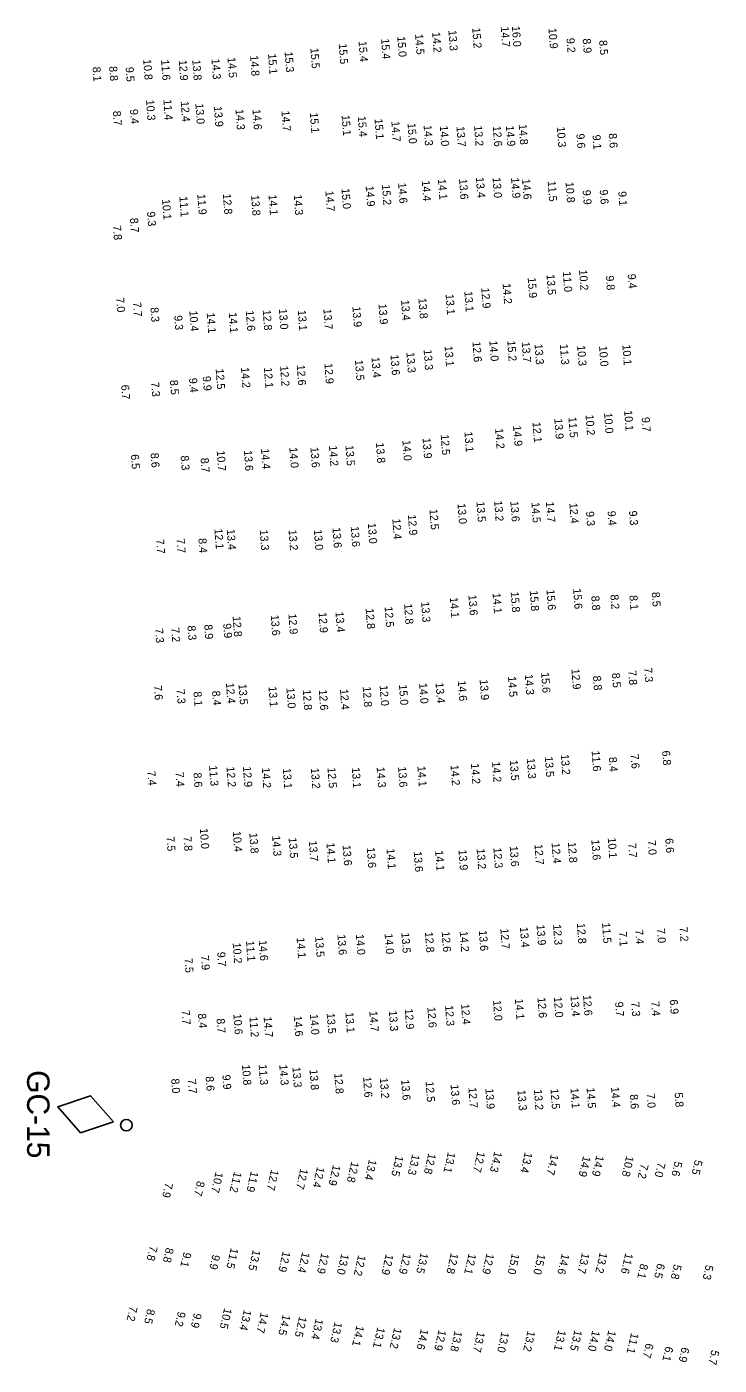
# Model space of a CAD drawing. Extents: x 815385 to 820851, y 582449 to 604245.
# Drawn here: x 820400 to 820832, y 590107 to 590943 of the extents above; entities that cross this region are included whole.
import ezdxf

# ---------------------------------------------------------------- set-up
doc = ezdxf.new("R2010")
doc.units = 0
doc.layers.add('V-CHAN-AIDS', color=7, linetype='Continuous')
doc.layers.add('V-TOPO-SOUN-021309', color=7, linetype='Continuous')

msp = doc.modelspace()

# ---------------------------------------------------------------- linework, layer by layer
at = {"layer": 'V-CHAN-AIDS'}
msp.add_lwpolyline([(820454.23, 590259), (820439.95, 590275.25), (820419.45, 590268.32), (820433.73, 590252.07)], close=True, dxfattribs=at)
msp.add_circle((820462.34, 590256.83), 3.6, dxfattribs=at)

# ---------------------------------------------------------------- texts
msp.add_text('GC-15', height=14, rotation=270, dxfattribs=at).set_placement((820400.36, 590291.23))
at = {"layer": 'V-TOPO-SOUN-021309'}
for s, rotation, p in [('14.7 ', 274.208, (820696.06, 590943.12)), ('16.0 ', 274.208, (820703.02, 590943.38)), ('15.4 ', 274.208, (820621.34, 590935.57)), ('15.0 ', 274.208, (820631.45, 590936.96)), ('14.5 ', 274.208, (820642.55, 590938.44)), ('14.2 ', 274.208, (820653.25, 590939.65)), ('13.3 ', 274.208, (820663.36, 590940.81)), ('15.2 ', 274.208, (820678.25, 590942.33)), ('10.9 ', 274.208, (820725.87, 590942.15)), ('9.2', 274.208, (820737.11, 590935.91)), ('8.9', 274.208, (820747.21, 590935.6)), ('8.5', 274.208, (820757.48, 590934.54)), ('15.1 ', 274.208, (820550.77, 590926.13)), ('15.3 ', 274.208, (820561.13, 590927.37)), ('15.5 ', 274.208, (820577.21, 590929.72)), ('15.5 ', 274.208, (820594.89, 590932.47)), ('15.4 ', 274.208, (820607.31, 590933.97)), ('8.1', 274.208, (820441.19, 590917.92)), ('8.8', 274.208, (820451.57, 590918.24)), ('9.5', 274.208, (820461.83, 590917.78)), ('10.8 ', 274.208, (820472.83, 590922.66)), ('11.6 ', 274.208, (820483.98, 590922.37)), ('12.9 ', 274.208, (820495.03, 590922.19)), ('13.8 ', 274.208, (820503.48, 590922.33)), ('14.3 ', 274.208, (820515.46, 590922.95)), ('14.5 ', 274.208, (820525.46, 590923.91)), ('14.8 ', 274.208, (820539.59, 590925.04)), ('10.3 ', 274.208, (820474.6, 590897.3)), ('11.4 ', 274.208, (820485.46, 590897.54)), ('12.4 ', 274.208, (820496.27, 590896.47)), ('13.0 ', 274.208, (820505.39, 590895.03)), ('13.9 ', 274.208, (820517, 590893.32)), ('8.7', 274.208, (820453.9, 590890.39)), ('9.4', 274.208, (820464.54, 590891.46)), ('14.3 ', 274.208, (820530.47, 590891.46)), ('14.6 ', 274.208, (820541.07, 590891.46)), ('14.7 ', 274.208, (820559.14, 590890.53)), ('15.1 ', 274.208, (820576.91, 590889.32)), ('15.1 ', 274.208, (820596.72, 590887.78)), ('15.4 ', 274.208, (820606.82, 590887.13)), ('15.1 ', 274.208, (820617.28, 590885.5)), ('14.7 ', 274.208, (820627.77, 590883.97)), ('15.0 ', 274.208, (820637.87, 590882.75)), ('14.3 ', 274.208, (820647.89, 590881.5)), ('14.0 ', 274.208, (820658.02, 590881.19)), ('13.7 ', 274.208, (820668.4, 590880.82)), ('13.2 ', 274.208, (820679.4, 590881.22)), ('12.6 ', 274.208, (820691.12, 590880.99)), ('14.9 ', 274.208, (820699.28, 590881.15)), ('14.8 ', 274.208, (820707.3, 590882.1)), ('10.3 ', 274.208, (820731.05, 590880.52)), ('9.6', 274.208, (820743.28, 590876.15)), ('8.6', 274.208, (820763.46, 590876.39)), ('9.1', 274.208, (820753.34, 590875.46)), ('14.9 ', 274.208, (820611.71, 590843.55)), ('15.2 ', 274.208, (820621.89, 590844.41)), ('14.6 ', 274.208, (820631.97, 590845.47)), ('14.4 ', 274.208, (820646.75, 590846.93)), ('14.1 ', 274.208, (820656.84, 590847.85)), ('13.6 ', 274.208, (820670, 590847.93)), ('13.4 ', 274.208, (820680.55, 590848.97)), ('13.0 ', 274.208, (820690.95, 590848.85)), ('14.9 ', 274.208, (820702.46, 590848.67)), ('14.6 ', 274.208, (820709.41, 590847.93)), ('11.5 ', 274.208, (820725.36, 590846.65)), ('10.8 ', 274.208, (820736.53, 590845.95)), ('10.1 ', 274.208, (820484.64, 590835.25)), ('11.1 ', 274.208, (820495.41, 590837.01)), ('11.9 ', 274.208, (820506.61, 590838.43)), ('12.8 ', 274.208, (820522.6, 590838.62)), ('13.8 ', 274.208, (820540.2, 590837.84)), ('14.1 ', 274.208, (820551.09, 590838.07)), ('14.3 ', 274.208, (820566.84, 590838.1)), ('14.7 ', 274.208, (820586.6, 590840.44)), ('15.0 ', 274.208, (820596.65, 590842.02)), ('9.9', 274.208, (820747.21, 590840.98)), ('9.6', 274.208, (820757.84, 590841.24)), ('9.1', 274.208, (820769.46, 590840.16)), ('9.3', 274.208, (820475.24, 590827.5)), ('7.8', 274.208, (820453.96, 590818.86)), ('8.7', 274.208, (820464.6, 590823.52)), ('15.9 ', 274.208, (820712.87, 590786.33)), ('13.5 ', 274.208, (820724.64, 590788.29)), ('11.0 ', 274.208, (820734.83, 590790.11)), ('10.2 ', 274.208, (820744.91, 590791.13)), ('9.8', 274.208, (820761.68, 590787.53)), ('9.4', 274.208, (820775.3, 590788.55)), ('13.1 ', 274.208, (820661.64, 590775.93)), ('13.1 ', 274.208, (820673.33, 590777.74)), ('12.9 ', 274.208, (820683.89, 590779.89)), ('14.2 ', 274.208, (820697.24, 590782.67)), ('7.0', 274.208, (820455.92, 590773.76)), ('7.7', 274.208, (820466.49, 590770.98)), ('8.3', 274.208, (820477.33, 590767.65)), ('13.9 ', 274.208, (820603.42, 590768.21)), ('13.9 ', 274.208, (820619.75, 590769.89)), ('13.4 ', 274.208, (820633.8, 590772.29)), ('13.8 ', 274.208, (820644.65, 590773.45)), ('9.3', 274.208, (820492.22, 590762.63)), ('10.4 ', 274.208, (820501.63, 590765.54)), ('14.1 ', 274.208, (820512.48, 590764.33)), ('14.1 ', 274.208, (820526.25, 590764.54)), ('12.6 ', 274.208, (820536.91, 590765.71)), ('12.8 ', 274.208, (820547.46, 590766.09)), ('13.0 ', 274.208, (820557.56, 590766.74)), ('13.1 ', 274.208, (820569.38, 590765.93)), ('13.7 ', 274.208, (820585.27, 590766.7)), ('13.1 ', 274.208, (820660.99, 590743.56)), ('12.6 ', 274.208, (820678.42, 590746.32)), ('14.0 ', 274.208, (820688.91, 590746.87)), ('15.2 ', 274.208, (820700.12, 590746.86)), ('13.7 ', 274.208, (820709.18, 590746.12)), ('13.3 ', 274.208, (820717.16, 590744.81)), ('11.3 ', 274.208, (820732.96, 590744.72)), ('10.3 ', 274.208, (820743.76, 590743.94)), ('10.0 ', 274.208, (820757.42, 590743.58)), ('10.1 ', 274.208, (820771.97, 590744.39)), ('13.5 ', 274.208, (820605.04, 590734.82)), ('13.4 ', 274.208, (820615.38, 590736.61)), ('13.6 ', 274.208, (820627.25, 590738.08)), ('13.3 ', 274.208, (820637.14, 590739.63)), ('13.3 ', 274.208, (820647.91, 590741.34)), ('12.5 ', 274.208, (820518.08, 590729.33)), ('14.2 ', 274.208, (820533.89, 590730.22)), ('12.1 ', 274.208, (820548.21, 590730.11)), ('12.2 ', 274.208, (820558.32, 590731.15)), ('12.6 ', 274.208, (820568.69, 590731.73)), ('12.9 ', 274.208, (820585.95, 590732.75)), ('6.7', 274.208, (820459.05, 590719.26)), ('7.3', 274.208, (820477.76, 590721.03)), ('8.5', 274.208, (820489.51, 590722.26)), ('9.4', 274.208, (820501.47, 590723.55)), ('9.9', 274.208, (820509.97, 590724.7)), ('10.2 ', 274.208, (820749.01, 590700.57)), ('10.0 ', 274.208, (820760.54, 590701.79)), ('10.1 ', 274.208, (820773.12, 590703.29)), ('14.2 ', 274.208, (820692.56, 590692.13)), ('14.9 ', 274.208, (820703.73, 590693.84)), ('12.1 ', 274.208, (820715.93, 590696)), ('13.9 ', 274.208, (820729.49, 590698.23)), ('11.5 ', 274.208, (820738.34, 590699.14)), ('9.7', 274.208, (820784.05, 590699.08)), ('14.0 ', 274.208, (820634.63, 590684.7)), ('13.9 ', 274.208, (820647.26, 590686.04)), ('12.5 ', 274.208, (820658.58, 590688.26)), ('13.1 ', 274.208, (820673.39, 590689.99)), ('6.5', 274.208, (820465.14, 590675.8)), ('8.6', 274.208, (820477.45, 590676.69)), ('8.3', 274.208, (820496.21, 590675.05)), ('10.7 ', 274.208, (820518.73, 590678.18)), ('13.6 ', 274.208, (820535.73, 590678.34)), ('14.4 ', 274.208, (820546.37, 590679.46)), ('14.0 ', 274.208, (820564.06, 590680.21)), ('13.6 ', 274.208, (820577.25, 590680.36)), ('14.2 ', 274.208, (820588.83, 590681.33)), ('13.5 ', 274.208, (820599.11, 590681.55)), ('13.8 ', 274.208, (820618.13, 590683.18)), ('8.7', 274.208, (820508.69, 590673.63)), ('13.0 ', 274.208, (820669.06, 590645.22)), ('13.5 ', 274.208, (820680.87, 590646.39)), ('13.2 ', 274.208, (820691.95, 590646.85)), ('13.6 ', 274.208, (820702.03, 590646.6)), ('14.5 ', 274.208, (820715.18, 590645.93)), ('14.7 ', 274.208, (820724.26, 590646.24)), ('12.4 ', 274.208, (820738.89, 590645.46)), ('12.4 ', 274.208, (820628.37, 590635.6)), ('12.9 ', 274.208, (820638.12, 590638.14)), ('12.5 ', 274.208, (820651.57, 590641.63)), ('9.3', 274.208, (820749.28, 590640.24)), ('9.4', 274.208, (820762.75, 590640.49)), ('9.3', 274.208, (820776.13, 590640.62)), ('12.1 ', 274.208, (820517.32, 590629.42)), ('13.4 ', 274.208, (820525, 590629.09)), ('13.3 ', 274.208, (820545.58, 590628.72)), ('13.2 ', 274.208, (820563.59, 590628.67)), ('13.0 ', 274.208, (820579.37, 590628.84)), ('13.6 ', 274.208, (820590.99, 590630.19)), ('13.6 ', 274.208, (820602.4, 590630.9)), ('13.0 ', 274.208, (820613.08, 590632.91)), ('7.7', 274.208, (820480.87, 590622.86)), ('7.7', 274.208, (820493.68, 590623.27)), ('8.4', 274.208, (820507.29, 590623.38)), ('15.6 ', 274.208, (820741.24, 590592.06)), ('13.3 ', 274.208, (820646.33, 590583.8)), ('14.1 ', 274.208, (820664.29, 590586.56)), ('13.6 ', 274.208, (820675.86, 590588.04)), ('14.1 ', 274.208, (820690.95, 590589.24)), ('15.8 ', 274.208, (820702.25, 590589.98)), ('15.8 ', 274.208, (820714.16, 590590.75)), ('15.6 ', 274.208, (820724.63, 590591.37)), ('8.8', 274.208, (820752.58, 590587.47)), ('8.2', 274.208, (820764.56, 590588.21)), ('8.1', 274.208, (820776.38, 590587.78)), ('8.5', 274.208, (820790.31, 590589.79)), ('13.6 ', 274.208, (820552.48, 590575.48)), ('12.9 ', 274.208, (820563.5, 590576.3)), ('12.9 ', 274.208, (820582.31, 590577.18)), ('13.4 ', 274.208, (820592.89, 590577.53)), ('12.8 ', 274.208, (820611.73, 590579.59)), ('12.5 ', 274.208, (820623.56, 590580.72)), ('12.8 ', 274.208, (820635.7, 590582.55)), ('7.3', 274.208, (820480.23, 590567.19)), ('7.2', 274.208, (820490.34, 590567.61)), ('8.3', 274.208, (820500.45, 590568.87)), ('8.9', 274.208, (820510.96, 590569.52)), ('9.9', 274.208, (820522.76, 590570.17)), ('12.8 ', 274.208, (820528.67, 590574.72)), ('12.9 ', 274.208, (820740.18, 590541.85)), ('7.3', 274.208, (820785.56, 590542.61)), ('13.4 ', 274.208, (820655.34, 590533.25)), ('14.6 ', 274.208, (820669.24, 590534.52)), ('13.9 ', 274.208, (820682.88, 590535.17)), ('14.5 ', 274.208, (820700.58, 590537.14)), ('14.3 ', 274.208, (820711.08, 590538.45)), ('15.6 ', 274.208, (820721.25, 590539.67)), ('8.8', 274.208, (820753.63, 590537.51)), ('8.5', 274.208, (820765.46, 590539.26)), ('7.8', 274.208, (820775.67, 590540.82)), ('7.6', 274.208, (820479.5, 590531.47)), ('7.3', 274.208, (820493.68, 590529.18)), ('8.1', 274.208, (820504.25, 590527.65)), ('8.4', 274.208, (820515.82, 590528.13)), ('12.4 ', 274.208, (820524.5, 590533.06)), ('13.5 ', 274.208, (820532.34, 590532.36)), ('13.1 ', 274.208, (820551.08, 590530.85)), ('13.0 ', 274.208, (820562.23, 590530.01)), ('12.8 ', 274.208, (820572.45, 590528.88)), ('12.6 ', 274.208, (820582.49, 590528.82)), ('12.4 ', 274.208, (820595.71, 590529.18)), ('12.8 ', 274.208, (820609.87, 590530.78)), ('12.0 ', 274.208, (820620.47, 590531.57)), ('15.0 ', 274.208, (820632.51, 590532.01)), ('14.0 ', 274.208, (820645.08, 590532.96)), ('14.2 ', 274.208, (820690.62, 590483.86)), ('13.5 ', 274.208, (820701.7, 590484.86)), ('13.3 ', 274.208, (820712.31, 590486.01)), ('13.5 ', 274.208, (820723.55, 590487.1)), ('13.2 ', 274.208, (820733.57, 590488.46)), ('11.6 ', 274.208, (820752.81, 590490.67)), ('8.4', 274.208, (820763.53, 590486.73)), ('7.6', 274.208, (820777.14, 590488.64)), ('6.8', 274.208, (820796.79, 590490.72)), ('7.4', 274.208, (820475.41, 590478.11)), ('7.4', 274.208, (820493.03, 590477.37)), ('8.6', 274.208, (820504.18, 590476.97)), ('11.3 ', 274.208, (820513.97, 590481.47)), ('12.2 ', 274.208, (820524.84, 590480.77)), ('12.9 ', 274.208, (820535.11, 590480.82)), ('14.2 ', 274.208, (820546.87, 590480.17)), ('13.1 ', 274.208, (820559.99, 590479.76)), ('13.2 ', 274.208, (820577.52, 590479.85)), ('12.5 ', 274.208, (820587.9, 590480.21)), ('13.1 ', 274.208, (820603.05, 590480.25)), ('14.3 ', 274.208, (820618.57, 590480.5)), ('13.6 ', 274.208, (820631.94, 590480.74)), ('14.1 ', 274.208, (820644.01, 590481.1)), ('14.2 ', 274.208, (820664.72, 590481.8)), ('14.2 ', 274.208, (820677.44, 590482.74)), ('10.0 ', 274.208, (820508.21, 590442.23)), ('7.5', 274.208, (820487.34, 590437.09)), ('7.8', 274.208, (820497.97, 590437.15)), ('10.4 ', 274.208, (820528.78, 590440.41)), ('13.8 ', 274.208, (820539.07, 590439.35)), ('14.3 ', 274.208, (820553.29, 590437.67)), ('13.5 ', 274.208, (820563.62, 590436.41)), ('13.7 ', 274.208, (820576.22, 590434.42)), ('14.1 ', 274.208, (820587.24, 590433.26)), ('12.4 ', 274.208, (820727.82, 590433.14)), ('12.8 ', 274.208, (820738, 590433.56)), ('13.6 ', 274.208, (820752.6, 590435.16)), ('10.1 ', 274.208, (820762.86, 590436.4)), ('7.7', 274.208, (820775.6, 590432.92)), ('7.0', 274.208, (820787.79, 590434.76)), ('6.6', 274.208, (820798.73, 590435.93)), ('13.6 ', 274.208, (820597.33, 590431.73)), ('13.6 ', 274.208, (820612.42, 590430.33)), ('14.1 ', 274.208, (820624.74, 590429.56)), ('13.6 ', 274.208, (820641.72, 590427.82)), ('14.1 ', 274.208, (820655.1, 590428.41)), ('13.9 ', 274.208, (820669.7, 590428.86)), ('13.2 ', 274.208, (820681.01, 590429.51)), ('12.3 ', 274.208, (820691.45, 590430.12)), ('13.6 ', 274.208, (820701.65, 590431.17)), ('12.7 ', 274.208, (820717.14, 590432.3)), ('12.8 ', 274.208, (820743.62, 590382.96)), ('11.5 ', 274.208, (820759.28, 590383.22)), ('13.5 ', 274.208, (820580.16, 590374.64)), ('13.6 ', 274.208, (820594.1, 590375.91)), ('14.0 ', 274.208, (820605.63, 590376.02)), ('14.0 ', 274.208, (820623.56, 590376.48)), ('13.5 ', 274.208, (820633.96, 590377.08)), ('12.8 ', 274.208, (820648.73, 590377.47)), ('12.6 ', 274.208, (820659.2, 590377.75)), ('14.2 ', 274.208, (820670.43, 590377.94)), ('13.6 ', 274.208, (820682.4, 590378.46)), ('12.7 ', 274.208, (820695.81, 590379.63)), ('13.4 ', 274.208, (820708.02, 590380.56)), ('13.9 ', 274.208, (820718.42, 590381.97)), ('12.3 ', 274.208, (820728.71, 590382.18)), ('7.1', 274.208, (820769.76, 590377.65)), ('7.4', 274.208, (820779.9, 590378.99)), ('7.0', 274.208, (820793.55, 590379.68)), ('7.2', 274.208, (820807.64, 590380.6)), ('10.2 ', 274.208, (820528.71, 590370.7)), ('11.1 ', 274.208, (820537.02, 590371.94)), ('14.6 ', 274.208, (820544.98, 590372.31)), ('14.1 ', 274.208, (820568.59, 590373.96)), ('7.5', 274.208, (820498.6, 590361.1)), ('7.9', 274.208, (820508.84, 590362.83)), ('9.7', 274.208, (820519.05, 590364.97)), ('12.4 ', 274.208, (820671.28, 590332.52)), ('12.0 ', 274.208, (820691.24, 590334.82)), ('14.1 ', 274.208, (820704.91, 590335.7)), ('12.6 ', 274.208, (820719.01, 590336.57)), ('12.0 ', 274.208, (820729.23, 590336.89)), ('13.4 ', 274.208, (820739.63, 590337.59)), ('12.6 ', 274.208, (820747.41, 590338.04)), ('9.7', 274.208, (820767.44, 590333.8)), ('7.3', 274.208, (820777.53, 590333.81)), ('7.4', 274.208, (820790.04, 590334.12)), ('6.9', 274.208, (820801.52, 590335.27)), ('7.7', 274.208, (820496.84, 590328.62)), ('8.4', 274.208, (820507.04, 590326.55)), ('10.6 ', 274.208, (820529.11, 590326.25)), ('11.2 ', 274.208, (820539.17, 590324.54)), ('14.7 ', 274.208, (820548.03, 590324.53)), ('14.6 ', 274.208, (820566.83, 590325.07)), ('14.0 ', 274.208, (820576.94, 590326.13)), ('13.5 ', 274.208, (820587.39, 590326.78)), ('13.1 ', 274.208, (820599.08, 590327.3)), ('14.7 ', 274.208, (820614.02, 590328.03)), ('13.3 ', 274.208, (820626.18, 590328.3)), ('12.9 ', 274.208, (820636.15, 590329.51)), ('12.6 ', 274.208, (820650.24, 590330.52)), ('12.3 ', 274.208, (820661.3, 590331.61)), ('8.7', 274.208, (820518.65, 590323.4)), ('10.8 ', 274.208, (820534.49, 590294.56)), ('11.3 ', 274.208, (820544.93, 590294.7)), ('14.3 ', 274.208, (820557.8, 590294.57)), ('13.3 ', 274.208, (820565.98, 590293.14)), ('13.8 ', 274.208, (820576.7, 590291.55)), ('8.0', 274.208, (820490.33, 590285.81)), ('7.7', 274.208, (820500.75, 590285.59)), ('8.6', 274.208, (820511.81, 590287.24)), ('9.9', 274.208, (820522.26, 590288.23)), ('12.8 ', 274.208, (820592.13, 590289.2)), ('12.6 ', 274.208, (820610.1, 590286.97)), ('13.2 ', 274.208, (820620.57, 590286.32)), ('13.6 ', 274.208, (820633.92, 590285.17)), ('12.5 ', 274.208, (820649.15, 590284.04)), ('13.6 ', 274.208, (820664.75, 590282.14)), ('12.7 ', 274.208, (820675.89, 590280.38)), ('13.9 ', 274.208, (820686.44, 590279.69)), ('13.3 ', 274.208, (820706.53, 590278.74)), ('13.2 ', 274.208, (820716.79, 590279.09)), ('12.5 ', 274.208, (820727.12, 590279.61)), ('14.1 ', 274.208, (820739.59, 590280.01)), ('14.5 ', 274.208, (820749.64, 590280.16)), ('14.4 ', 274.208, (820764.9, 590280.64)), ('8.6', 274.208, (820776.67, 590275.99)), ('7.0', 274.208, (820787.16, 590276.64)), ('5.8', 274.208, (820804.6, 590277.15)), ('12.7 ', 257.192, (820681.59, 590240.67)), ('14.3 ', 257.192, (820692.14, 590240.75)), ('12.9 ', 257.192, (820591.36, 590232.34)), ('12.8 ', 257.192, (820602.83, 590234.34)), ('13.4 ', 257.192, (820613.88, 590235.76)), ('13.5 ', 257.192, (820630.59, 590238.16)), ('13.3 ', 257.192, (820640.85, 590238.96)), ('12.8 ', 257.192, (820650.94, 590239.58)), ('13.1 ', 257.192, (820663.14, 590240.28)), ('13.4 ', 257.192, (820711.15, 590240.26)), ('14.7 ', 257.192, (820727.43, 590239)), ('14.9 ', 257.192, (820747.51, 590237.86)), ('14.9 ', 257.192, (820755.81, 590238.19)), ('10.8 ', 257.192, (820774.47, 590237.96)), ('7.2', 257.192, (820783.61, 590233.06)), ('7.0', 257.192, (820794.15, 590233.99)), ('5.6', 257.192, (820804.66, 590234.55)), ('5.5', 257.192, (820817.31, 590235.5)), ('10.7 ', 257.192, (820518.07, 590227.9)), ('11.2 ', 257.192, (820529.61, 590228.08)), ('11.9 ', 257.192, (820540.1, 590228.34)), ('12.7 ', 257.192, (820552.75, 590229.37)), ('12.7 ', 257.192, (820571.05, 590230.09)), ('12.4 ', 257.192, (820581.43, 590231.11)), ('7.9', 257.192, (820486.66, 590221.21)), ('8.7', 257.192, (820506.55, 590222.28)), ('7.8', 257.192, (820477.03, 590181.76)), ('8.8', 257.192, (820487.16, 590180.62)), ('9.1', 257.192, (820498.05, 590177.82)), ('9.9', 257.192, (820516.13, 590176.31)), ('11.5 ', 257.192, (820527.6, 590180.48)), ('13.5 ', 257.192, (820541.34, 590179.29)), ('12.9 ', 257.192, (820560.01, 590178.36)), ('12.4 ', 257.192, (820572.17, 590177.83)), ('12.9 ', 257.192, (820584.14, 590177.32)), ('13.0 ', 257.192, (820596.58, 590176.79)), ('12.2 ', 257.192, (820607.13, 590175.97)), ('12.9 ', 257.192, (820624.37, 590176.6)), ('12.9 ', 257.192, (820635.3, 590177.08)), ('13.5 ', 257.192, (820646.1, 590177.42)), ('12.8 ', 257.192, (820664.97, 590177.26)), ('12.1 ', 257.192, (820676.06, 590176.95)), ('12.9 ', 257.192, (820687.27, 590177.06)), ('15.0 ', 257.192, (820703.09, 590176.94)), ('15.0 ', 257.192, (820719.24, 590176.78)), ('14.6 ', 257.192, (820734.23, 590176.88)), ('13.7 ', 257.192, (820746.77, 590177.39)), ('13.2 ', 257.192, (820757.96, 590177.63)), ('11.6 ', 257.192, (820773.92, 590177.24)), ('8.1', 257.192, (820783.35, 590170.64)), ('6.5', 257.192, (820793.82, 590170.81)), ('5.8', 257.192, (820804.22, 590170.2)), ('5.3', 257.192, (820824.15, 590169.92)), ('7.2', 257.192, (820464.53, 590144.06)), ('8.5', 257.192, (820475.44, 590142.37)), ('9.2', 257.192, (820494.58, 590140.74)), ('10.5 ', 257.192, (820523.47, 590142.85)), ('13.4 ', 257.192, (820535.75, 590141.83)), ('9.9', 257.192, (820504.59, 590139.82)), ('14.7 ', 257.192, (820546.28, 590140.2)), ('14.5 ', 257.192, (820560.02, 590138.83)), ('12.5 ', 257.192, (820570.28, 590137.67)), ('13.4 ', 257.192, (820580.57, 590136.21)), ('13.3 ', 257.192, (820592.42, 590134.22)), ('14.1 ', 257.192, (820606.07, 590132.03)), ('13.1 ', 257.192, (820619.1, 590130.93)), ('13.2 ', 257.192, (820629.58, 590130.54)), ('14.6 ', 257.192, (820646.26, 590129.85)), ('12.9 ', 257.192, (820657.34, 590129.27)), ('13.8 ', 257.192, (820667.34, 590128.64)), ('13.7 ', 257.192, (820681.48, 590128.18)), ('13.0 ', 257.192, (820696.64, 590128.07)), ('13.2 ', 257.192, (820712.9, 590128.72)), ('13.1 ', 257.192, (820732.07, 590129.16)), ('13.5 ', 257.192, (820742.14, 590129.17)), ('14.0 ', 257.192, (820753.28, 590128.87)), ('14.0 ', 257.192, (820763.34, 590128.97)), ('11.1 ', 257.192, (820777.52, 590127.36)), ('6.7', 257.192, (820786.74, 590120.93)), ('6.1', 257.192, (820799.01, 590118.94)), ('6.9', 257.192, (820809.14, 590118.45)), ('5.7', 257.192, (820827.71, 590116.73))]:
    msp.add_text(s, height=5, rotation=rotation, dxfattribs=at).set_placement(p)

doc.saveas('drawing.dxf')
